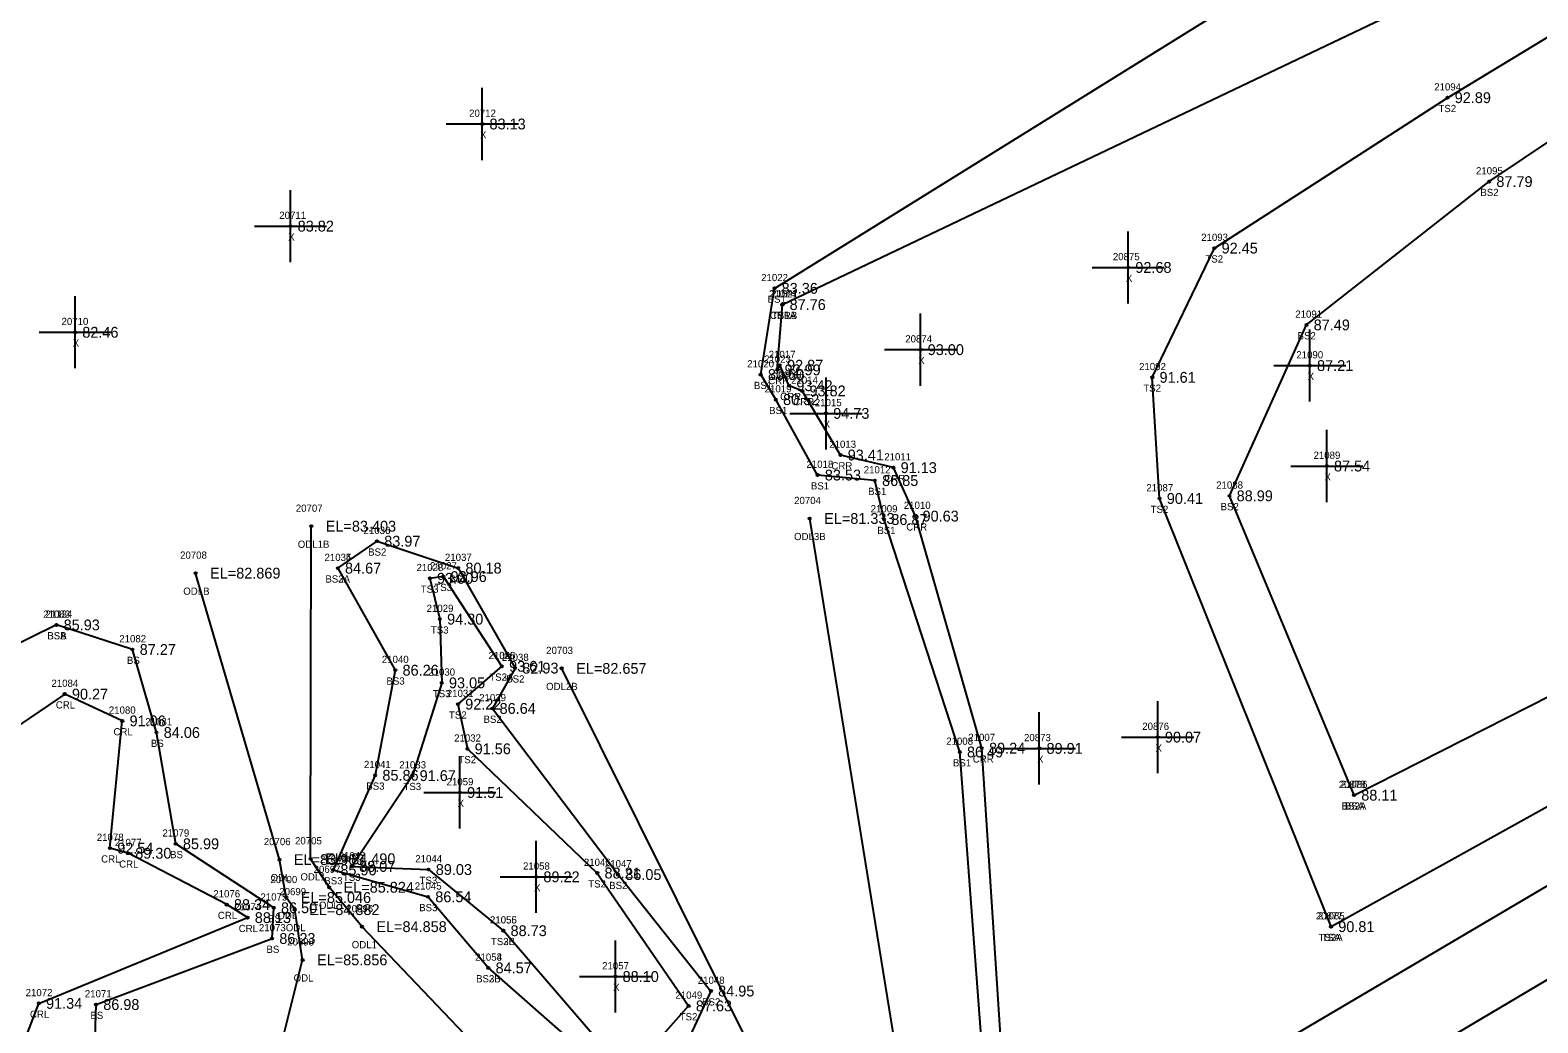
# Model space of a CAD drawing. Extents: x 2530197 to 2532051, y 935230 to 936631.
# Drawn here: x 2531049.2 to 2531258.3, y 936035.9 to 936173.5 of the extents above; entities that cross this region are included whole.
import ezdxf

# ---------------------------------------------------------------- set-up
doc = ezdxf.new("R2010")
doc.units = 0
for name, color, linetype in [('RD_DTM_BkLn1', 7, 'Continuous'), ('RD_DTM_BkLn2', 7, 'Continuous'), ('RD_DTM_BkLn_txCode', 7, 'Continuous'), ('RD_EX_H2O', 7, 'Continuous'), ('RD_EX_H2O_txCode', 7, 'Continuous'), ('RD_EX_Misc', 7, 'Continuous'), ('RD_EX_Misc_txCode', 7, 'Continuous'), ('RD_EX_Road', 7, 'Continuous'), ('RD_EX_TX_H2O_ELEV', 7, 'Continuous'), ('RD_EX_TX_Misc_ELEV', 7, 'Continuous'), ('RD_SMD_Locator', 7, 'Continuous')]:
    doc.layers.add(name, color=color, linetype=linetype)

msp = doc.modelspace()

# ---------------------------------------------------------------- linework, layer by layer
at = {"layer": 'RD_DTM_BkLn1'}
msp.add_lwpolyline([(2531175.16, 935992.09), (2531214.08, 936014.93), (2531297.2, 936064.16), (2531382.2, 936114.3), (2531466.12, 936163.77), (2531548.89, 936212.96), (2531632.55, 936261.89), (2531678, 936289.19), (2531722.34, 936315.93), (2531754.26, 936342.49), (2531759.78, 936349.83), (2531772.77, 936373.29), (2531778.96, 936389.71), (2531793.78, 936438.29), (2531813.65, 936511.36), (2531832.39, 936582.88)], dxfattribs=at)
at = {"layer": 'RD_DTM_BkLn2'}
for points in [[(2531151.41, 935999.3), (2531167.24, 936008.08), (2531181.24, 936018.79), (2531181.58, 936027.3), (2531178.12, 936073.45), (2531167.63, 936105.68), (2531166.35, 936111.09), (2531158.41, 936111.85), (2531152.62, 936122.31), (2531150.51, 936125.78), (2531152.42, 936137.74), (2531230.98, 936186.53), (2531313.57, 936233.84), (2531368.67, 936272.3), (2531431.6, 936307.72), (2531489.09, 936344.56)], [(2531153.52, 936135.49), (2531238.65, 936176.03), (2531319.12, 936225.52), (2531376.31, 936260.58), (2531439.07, 936295.88), (2531496.33, 936332.58)], [(2531229.61, 936049.23), (2531205.83, 936108.6), (2531204.82, 936125.4), (2531213.43, 936143.32), (2531245.76, 936164.18), (2531307.39, 936201.57), (2531320.27, 936194.22), (2531339.05, 936206.18), (2531339.67, 936220.33), (2531381.85, 936240.08), (2531451.4, 936278.23)], [(2531232.8, 936067.46), (2531215.52, 936108.97), (2531226.2, 936132.67), (2531251.54, 936152.54), (2531308.69, 936190.88), (2531325.04, 936186.59), (2531344.92, 936198.09), (2531350.73, 936212.74), (2531384.02, 936231.34), (2531448.45, 936270.32)], [(2531232.8, 936067.46), (2531281.18, 936092.01), (2531356.28, 936135.72), (2531362.71, 936151.65), (2531400.38, 936163.66), (2531430.03, 936179.35), (2531446.05, 936177.07), (2531452.65, 936188.16), (2531481.32, 936210.45), (2531494.44, 936219.29)], [(2531229.61, 936049.23), (2531287.21, 936081.23), (2531360.99, 936124.94), (2531368.39, 936145.81), (2531399.09, 936157.58), (2531431.15, 936172.97), (2531448.86, 936171.41), (2531455.43, 936183.06), (2531483.94, 936207.52), (2531496.93, 936216.06)], [(2531052.84, 936091.07), (2531024.22, 936076.99), (2530987.08, 936088.8), (2530959.02, 936078.33), (2530937.87, 936100.94), (2530909.67, 936126.05), (2530891.79, 936131.19), (2530874.19, 936136.38), (2530849.99, 936134.78), (2530837.59, 936141.92), (2530795.33, 936166.72)], [(2531091.86, 936098.94), (2531097.3, 936102.68), (2531108.56, 936098.95), (2531116.45, 936085.08), (2531113.3, 936079.49), (2531130.73, 936056.45), (2531143.61, 936040.3), (2531137.78, 936027.8), (2531130.84, 936027.63), (2531112.74, 936043.51)], [(2531091.86, 936098.94), (2531099.84, 936084.79), (2531097.05, 936070.22), (2531091.22, 936057.09), (2531104.38, 936053.37), (2531112.74, 936043.51)], [(2531114.62, 936085.33), (2531106.5, 936097.77), (2531104.62, 936097.53), (2531106.02, 936091.87), (2531106.28, 936083.04), (2531102.21, 936070.17), (2531093.82, 936057.58), (2531104.45, 936057.15), (2531114.82, 936048.67)], [(2531095.07, 935962.75), (2531085.58, 935955.64), (2531075.72, 935969.56), (2531061.95, 935983.33), (2531057.75, 936018.9), (2531058.33, 936038.43), (2531082.75, 936047.59), (2531082.98, 936051.85), (2531069.38, 936060.72), (2531066.72, 936076.15), (2531063.39, 936087.66), (2531052.84, 936091.07)], [(2531114.62, 936085.33), (2531108.53, 936080.08), (2531109.84, 936073.89), (2531127.85, 936056.66), (2531140.52, 936038.24), (2531132.03, 936028.68), (2531114.82, 936048.67)]]:
    msp.add_lwpolyline(points, dxfattribs=at)
at = {"layer": 'RD_EX_H2O'}
for points in [[(2531078.88, 935952.28), (2531078.88, 935952.28), (2531082.9, 935955.37), (2531071.89, 935962.43), (2531052.52, 935981.82), (2531042.66, 936018.54), (2531050.4, 936038.59), (2531079.35, 936050.48), (2531076.46, 936052.29), (2531062.77, 936059.41), (2531060.27, 936060.12), (2531061.98, 936077.76), (2531053.99, 936081.48), (2531023.23, 936060.57), (2531009.04, 936063.64), (2530981.92, 936072.85), (2530952.28, 936069.69), (2530922.53, 936086.42), (2530896.36, 936118.01), (2530886.54, 936120.09), (2530870.44, 936126.5), (2530844.88, 936119.11), (2530827.4, 936131.93), (2530794.88, 936161.74)], [(2531169.61, 936003.09), (2531185.12, 936014.09), (2531186.37, 936023.16), (2531184.04, 936029.91), (2531181.18, 936073.98), (2531171.96, 936106.16), (2531168.92, 936112.88), (2531161.58, 936114.63), (2531156.28, 936123.52), (2531154.46, 936124.24), (2531153.17, 936127.08), (2531152.81, 936126.44), (2531153.52, 936135.49)], [(2531123.96, 935982.91), (2531112.3, 936031.32), (2531095.21, 936049.23), (2531090.66, 936054.69), (2531088.09, 936058.64), (2531088.19, 936104.76)], [(2531151.41, 935999.3), (2531169.2, 936032.55), (2531157.31, 936105.83)], [(2531095.07, 935962.75), (2531077.48, 936006.74), (2531086.98, 936044.62), (2531085.89, 936051.59), (2531084.72, 936053.27), (2531083.78, 936058.53), (2531072.15, 936098.25)], [(2531140.12, 935992.42), (2531149.6, 936031.44), (2531122.92, 936085.04)]]:
    msp.add_lwpolyline(points, dxfattribs=at)
at = {"layer": 'RD_EX_Misc'}
for p, q in [((2531111.9, 936155.53), (2531111.9, 936165.53)), ((2531106.9, 936160.53), (2531116.9, 936160.53)), ((2531085.3, 936141.37), (2531085.3, 936151.37)), ((2531080.3, 936146.37), (2531090.3, 936146.37)), ((2531201.47, 936135.64), (2531201.47, 936145.64)), ((2531196.47, 936140.64), (2531206.47, 936140.64)), ((2531055.43, 936126.65), (2531055.43, 936136.65)), ((2531172.67, 936124.24), (2531172.67, 936134.24)), ((2531050.43, 936131.65), (2531060.43, 936131.65)), ((2531226.67, 936122.03), (2531226.67, 936132.03)), ((2531167.67, 936129.24), (2531177.67, 936129.24)), ((2531221.67, 936127.03), (2531231.67, 936127.03)), ((2531159.57, 936115.4), (2531159.57, 936125.4)), ((2531154.57, 936120.4), (2531164.57, 936120.4)), ((2531229.02, 936108.1), (2531229.02, 936118.1)), ((2531224.02, 936113.1), (2531234.02, 936113.1)), ((2531189.15, 936068.95), (2531189.15, 936078.95)), ((2531205.57, 936070.51), (2531205.57, 936080.51)), ((2531200.57, 936075.51), (2531210.57, 936075.51)), ((2531108.79, 936062.83), (2531108.79, 936072.83)), ((2531184.15, 936073.95), (2531194.15, 936073.95)), ((2531103.79, 936067.83), (2531113.79, 936067.83)), ((2531119.38, 936051.14), (2531119.38, 936061.14)), ((2531114.38, 936056.14), (2531124.38, 936056.14)), ((2531130.36, 936037.31), (2531130.36, 936047.31)), ((2531125.36, 936042.31), (2531135.36, 936042.31))]:
    msp.add_line(p, q, dxfattribs=at)
at = {"layer": 'RD_EX_Road'}
msp.add_lwpolyline([(2531169.65, 936000.77), (2531208.79, 936024.95), (2531292.04, 936074.02), (2531376.24, 936123.7), (2531460.37, 936174.49), (2531542.92, 936223.44), (2531626.67, 936270.85), (2531672.4, 936298.39), (2531714.28, 936327.21), (2531747.19, 936360.45), (2531761.42, 936377.32), (2531773.11, 936411.11), (2531782.2, 936441.65), (2531803.17, 936514.76), (2531820.28, 936585.8)], dxfattribs=at)
at = {"layer": 'RD_SMD_Locator'}
for centre in [(2531245.76, 936164.18), (2531111.9, 936160.53), (2531251.54, 936152.54), (2531085.3, 936146.37), (2531213.43, 936143.32), (2531201.47, 936140.64), (2531152.42, 936137.74), (2531153.52, 936135.49), (2531153.52, 936135.49), (2531055.43, 936131.65), (2531226.2, 936132.67), (2531172.67, 936129.24), (2531153.17, 936127.08), (2531226.67, 936127.03), (2531150.51, 936125.78), (2531152.81, 936126.44), (2531204.82, 936125.4), (2531154.46, 936124.24), (2531156.28, 936123.52), (2531152.62, 936122.31), (2531159.57, 936120.4), (2531161.58, 936114.63), (2531168.92, 936112.88), (2531229.02, 936113.1), (2531158.41, 936111.85), (2531166.35, 936111.09), (2531205.83, 936108.6), (2531215.52, 936108.97), (2531157.31, 936105.83), (2531171.96, 936106.16), (2531088.19, 936104.76), (2531167.63, 936105.68), (2531097.3, 936102.68), (2531072.15, 936098.25), (2531091.86, 936098.94), (2531091.86, 936098.94), (2531104.62, 936097.53), (2531106.5, 936097.77), (2531108.56, 936098.95), (2531106.02, 936091.87), (2531052.84, 936091.07), (2531052.84, 936091.07), (2531063.39, 936087.66), (2531114.62, 936085.33), (2531114.62, 936085.33), (2531116.45, 936085.08), (2531122.92, 936085.04), (2531099.84, 936084.79), (2531106.28, 936083.04), (2531053.99, 936081.48), (2531108.53, 936080.08), (2531113.3, 936079.49), (2531061.98, 936077.76), (2531066.72, 936076.15), (2531205.57, 936075.51), (2531109.84, 936073.89), (2531178.12, 936073.45), (2531181.18, 936073.98), (2531189.15, 936073.95), (2531097.05, 936070.22), (2531102.21, 936070.17), (2531108.79, 936067.83), (2531232.8, 936067.46), (2531232.8, 936067.46), (2531060.27, 936060.12), (2531069.38, 936060.72), (2531062.77, 936059.41), (2531083.78, 936058.53), (2531088.09, 936058.64), (2531091.22, 936057.09), (2531093.82, 936057.58), (2531104.45, 936057.15), (2531119.38, 936056.14), (2531127.85, 936056.66), (2531130.73, 936056.45), (2531090.66, 936054.69), (2531076.46, 936052.29), (2531082.98, 936051.85), (2531084.72, 936053.27), (2531085.89, 936051.59), (2531104.38, 936053.37), (2531079.35, 936050.48), (2531082.75, 936047.59), (2531095.21, 936049.23), (2531114.82, 936048.67), (2531114.82, 936048.67), (2531229.61, 936049.23), (2531229.61, 936049.23), (2531086.98, 936044.62), (2531112.74, 936043.51), (2531112.74, 936043.51), (2531130.36, 936042.31), (2531143.61, 936040.3), (2531050.4, 936038.59), (2531058.33, 936038.43), (2531140.52, 936038.24)]:
    msp.add_circle(centre, 0.15, dxfattribs=at)

# ---------------------------------------------------------------- texts
at = {"layer": 'RD_DTM_BkLn_txCode'}
for s, p in [('21094', (2531243.92, 936165.18)), ('TS2', (2531244.51, 936162.18)), ('21095', (2531249.71, 936153.54)), ('BS2', (2531250.32, 936150.54)), ('21093', (2531211.6, 936144.32)), ('TS2', (2531212.19, 936141.32)), ('21022', (2531150.58, 936138.74)), ('21021', (2531151.97, 936136.49)), ('BS1', (2531151.47, 936135.74)), ('TS1A', (2531152.07, 936133.49)), ('21091', (2531224.65, 936133.67)), ('BS2', (2531224.97, 936130.67)), ('21020', (2531148.64, 936126.78)), ('21092', (2531202.99, 936126.4)), ('BS1', (2531149.57, 936123.78)), ('21019', (2531151.06, 936123.31)), ('TS2', (2531203.58, 936123.4)), ('BS1', (2531151.67, 936120.31)), ('21018', (2531156.86, 936112.85)), ('21012', (2531164.8, 936112.09)), ('BS1', (2531157.47, 936109.85)), ('21087', (2531204, 936109.6)), ('21088', (2531213.68, 936109.97)), ('BS1', (2531165.41, 936109.09)), ('21009', (2531165.76, 936106.68)), ('TS2', (2531204.59, 936106.6)), ('BS2', (2531214.29, 936106.97)), ('21036', (2531095.44, 936103.68)), ('BS1', (2531166.69, 936103.68)), ('21034', (2531090.02, 936099.94)), ('21035', (2531090.02, 936099.94)), ('BS2', (2531096.07, 936100.68)), ('21027', (2531104.66, 936098.77)), ('21037', (2531106.72, 936099.95)), ('BS2A', (2531090.14, 936096.94)), ('BS3A', (2531090.14, 936096.94)), ('21028', (2531102.78, 936098.53)), ('BS2', (2531107.33, 936096.95)), ('TS3', (2531103.37, 936095.53)), ('TS3', (2531105.26, 936095.77)), ('21029', (2531104.18, 936092.87)), ('21083', (2531051.01, 936092.07)), ('21134', (2531051.33, 936092.07)), ('BSA', (2531051.57, 936089.07)), ('BSB', (2531051.59, 936089.07)), ('21082', (2531061.56, 936088.66)), ('TS3', (2531104.77, 936089.87)), ('21026', (2531112.76, 936086.33)), ('21025', (2531112.78, 936086.33)), ('BS', (2531062.62, 936085.66)), ('21040', (2531097.97, 936085.79)), ('21038', (2531114.62, 936086.08)), ('BS3', (2531098.61, 936082.79)), ('21030', (2531104.41, 936084.04)), ('TS2A', (2531112.88, 936083.33)), ('TS3A', (2531112.88, 936083.33)), ('BS2', (2531115.22, 936083.08)), ('TS3', (2531105.04, 936081.04)), ('21031', (2531106.98, 936081.08)), ('21039', (2531111.47, 936080.49)), ('TS2', (2531107.28, 936078.08)), ('21081', (2531065.17, 936077.15)), ('BS2', (2531112.07, 936077.49)), ('BS', (2531065.94, 936074.15)), ('21032', (2531108, 936074.89)), ('21008', (2531176.24, 936074.45)), ('TS2', (2531108.59, 936071.89)), ('21041', (2531095.49, 936071.22)), ('21033', (2531100.38, 936071.17)), ('BS1', (2531177.17, 936071.45)), ('BS3', (2531095.82, 936068.22)), ('TS3', (2531100.97, 936068.17)), ('20878', (2531230.68, 936068.46)), ('21086', (2531230.94, 936068.46)), ('BS2A', (2531231.08, 936065.46)), ('BSA', (2531231.53, 936065.46)), ('21079', (2531067.54, 936061.72)), ('BS', (2531068.6, 936058.72)), ('21043', (2531089.39, 936058.09)), ('21042', (2531091.98, 936058.58)), ('21044', (2531102.61, 936058.15)), ('21046', (2531125.99, 936057.66)), ('21047', (2531128.9, 936057.45)), ('BS3', (2531089.99, 936055.09)), ('TS3', (2531092.57, 936055.58)), ('TS3', (2531103.2, 936055.15)), ('21075', (2531081.14, 936052.85)), ('21045', (2531102.54, 936054.37)), ('TS2', (2531126.6, 936054.66)), ('BS2', (2531129.5, 936054.45)), ('BS3', (2531103.15, 936051.37)), ('21073', (2531080.92, 936048.59)), ('BS', (2531082.2, 936049.85)), ('21056', (2531112.96, 936049.67)), ('21055', (2531112.98, 936049.67)), ('20877', (2531227.5, 936050.23)), ('21085', (2531227.78, 936050.23)), ('TS2B', (2531113.1, 936046.67)), ('TS3B', (2531113.1, 936046.67)), ('TS2A', (2531227.88, 936047.23)), ('TSA', (2531228.33, 936047.23)), ('BS', (2531081.97, 936045.59)), ('21053', (2531110.91, 936044.51)), ('21054', (2531110.91, 936044.51)), ('BS2B', (2531111.04, 936041.51)), ('BS3B', (2531111.04, 936041.51)), ('21048', (2531141.78, 936041.3)), ('21071', (2531056.78, 936039.43)), ('21049', (2531138.69, 936039.24)), ('BS2', (2531142.38, 936038.3)), ('BS', (2531057.55, 936036.43)), ('TS2', (2531139.28, 936036.24))]:
    msp.add_text(s, height=1, dxfattribs=at).set_placement(p)
at = {"layer": 'RD_EX_H2O_txCode'}
for s, p in [('21024', (2531151.68, 936136.49)), ('CRRB', (2531151.79, 936133.49)), ('21017', (2531151.62, 936128.08)), ('21023', (2531150.98, 936127.44)), ('CRR', (2531151.56, 936124.44)), ('CRR', (2531151.92, 936125.08)), ('21016', (2531152.89, 936125.24)), ('21014', (2531154.73, 936124.52)), ('CRR', (2531153.21, 936122.24)), ('CRR', (2531155.03, 936121.52)), ('21013', (2531160.02, 936115.63)), ('21011', (2531167.65, 936113.88)), ('CRR', (2531160.32, 936112.63)), ('CRR', (2531167.66, 936110.88)), ('20704', (2531155.15, 936107.83)), ('21010', (2531170.36, 936107.16)), ('20707', (2531086.04, 936106.76)), ('CRR', (2531170.7, 936104.16)), ('ODL1B', (2531086.31, 936101.76)), ('ODL3B', (2531155.14, 936102.83)), ('20708', (2531069.99, 936100.25)), ('ODLB', (2531070.43, 936095.25)), ('20703', (2531120.76, 936087.04)), ('21084', (2531052.15, 936082.48)), ('ODL2B', (2531120.75, 936082.04)), ('CRL', (2531052.76, 936079.48)), ('21080', (2531060.11, 936078.76)), ('CRL', (2531060.75, 936075.76)), ('21007', (2531179.3, 936074.98)), ('CRR', (2531179.93, 936071.98)), ('21078', (2531058.44, 936061.12)), ('21077', (2531060.93, 936060.41)), ('20706', (2531081.6, 936060.53)), ('20705', (2531085.93, 936060.64)), ('CRL', (2531059.04, 936058.12)), ('CRL', (2531061.54, 936057.41)), ('20700', (2531082.52, 936055.27)), ('ODL', (2531082.54, 936055.53)), ('ODL1', (2531086.68, 936055.64)), ('20697', (2531088.51, 936056.69)), ('21076', (2531074.6, 936053.29)), ('20699', (2531083.75, 936053.59)), ('21074', (2531077.52, 936051.48)), ('ODL1', (2531089.25, 936051.69)), ('20696', (2531093.04, 936051.23)), ('CRL', (2531075.23, 936050.29)), ('ODL', (2531083.48, 936050.27)), ('ODL', (2531084.65, 936048.59)), ('CRL', (2531078.12, 936048.48)), ('20698', (2531084.84, 936046.62)), ('ODL1', (2531093.8, 936046.23)), ('ODL', (2531085.74, 936041.62)), ('21072', (2531048.57, 936039.59)), ('CRL', (2531049.17, 936036.59))]:
    msp.add_text(s, height=1, dxfattribs=at).set_placement(p)
at = {"layer": 'RD_EX_Misc_txCode'}
for s, p in [('20712', (2531110.07, 936161.53)), ('X', (2531111.59, 936158.53)), ('20711', (2531083.75, 936147.37)), ('X', (2531084.99, 936144.37)), ('20875', (2531199.35, 936141.64)), ('X', (2531201.16, 936138.64)), ('20710', (2531053.55, 936132.65)), ('20874', (2531170.56, 936130.24)), ('X', (2531055.11, 936129.65)), ('21090', (2531224.8, 936128.03)), ('X', (2531172.36, 936127.24)), ('X', (2531226.36, 936125.03)), ('21015', (2531158.02, 936121.4)), ('X', (2531159.25, 936118.4)), ('21089', (2531227.18, 936114.1)), ('X', (2531228.7, 936111.1)), ('20876', (2531203.43, 936076.51)), ('20873', (2531187.03, 936074.95)), ('X', (2531188.84, 936071.95)), ('X', (2531205.26, 936073.51)), ('21059', (2531106.95, 936068.83)), ('X', (2531108.47, 936065.83)), ('21058', (2531117.55, 936057.14)), ('X', (2531119.07, 936054.14)), ('21057', (2531128.52, 936043.31)), ('X', (2531130.04, 936040.31))]:
    msp.add_text(s, height=1, dxfattribs=at).set_placement(p)
at = {"layer": 'RD_EX_TX_H2O_ELEV'}
for s, p in [('87.76', (2531154.52, 936134.74)), ('92.99', (2531153.81, 936125.69)), ('92.87', (2531154.17, 936126.33)), ('93.42', (2531155.46, 936123.49)), ('93.82', (2531157.28, 936122.77)), ('93.41', (2531162.58, 936113.88)), ('91.13', (2531169.92, 936112.13)), ('EL=81.333', (2531159.31, 936105.08)), ('90.63', (2531172.96, 936105.41)), ('EL=83.403', (2531090.19, 936104.01)), ('EL=82.869', (2531074.15, 936097.5)), ('EL=82.657', (2531124.92, 936084.29)), ('90.27', (2531054.99, 936080.73)), ('91.06', (2531062.98, 936077.01)), ('89.24', (2531182.18, 936073.23)), ('92.54', (2531061.27, 936059.37)), ('89.30', (2531063.77, 936058.66)), ('EL=83.963', (2531085.78, 936057.78)), ('EL=84.490', (2531090.09, 936057.89)), ('EL=85.046', (2531086.72, 936052.52)), ('EL=85.824', (2531092.66, 936053.94)), ('88.34', (2531077.46, 936051.54)), ('EL=84.882', (2531087.89, 936050.84)), ('88.13', (2531080.35, 936049.73)), ('EL=84.858', (2531097.21, 936048.48)), ('EL=85.856', (2531088.98, 936043.87)), ('91.34', (2531051.4, 936037.84))]:
    msp.add_text(s, height=1.5, dxfattribs=at).set_placement(p)
at = {"layer": 'RD_EX_TX_Misc_ELEV'}
for s, p in [('92.89', (2531246.76, 936163.43)), ('83.13', (2531112.9, 936159.78)), ('87.79', (2531252.54, 936151.79)), ('83.82', (2531086.3, 936145.62)), ('92.45', (2531214.43, 936142.57)), ('92.68', (2531202.47, 936139.89)), ('83.36', (2531153.42, 936136.99)), ('87.76', (2531154.52, 936134.74)), ('87.49', (2531227.2, 936131.92)), ('82.46', (2531056.43, 936130.9)), ('93.00', (2531173.67, 936128.49)), ('87.21', (2531227.67, 936126.28)), ('80.60', (2531151.51, 936125.03)), ('91.61', (2531205.82, 936124.65)), ('80.52', (2531153.62, 936121.56)), ('94.73', (2531160.57, 936119.65)), ('83.53', (2531159.41, 936111.1)), ('87.54', (2531230.02, 936112.35)), ('86.85', (2531167.35, 936110.34)), ('90.41', (2531206.83, 936107.85)), ('88.99', (2531216.52, 936108.22)), ('86.87', (2531168.63, 936104.93)), ('83.97', (2531098.3, 936101.93)), ('84.67', (2531092.86, 936098.19)), ('84.67', (2531092.86, 936098.19)), ('80.18', (2531109.56, 936098.2)), ('93.00', (2531105.62, 936096.78)), ('92.96', (2531107.5, 936097.02)), ('85.93', (2531053.84, 936090.32)), ('85.93', (2531053.84, 936090.32)), ('94.30', (2531107.02, 936091.12)), ('87.27', (2531064.39, 936086.91)), ('86.26', (2531100.84, 936084.04)), ('93.61', (2531115.62, 936084.58)), ('93.61', (2531115.62, 936084.58)), ('82.93', (2531117.45, 936084.33)), ('93.05', (2531107.28, 936082.29)), ('92.22', (2531109.53, 936079.33)), ('86.64', (2531114.3, 936078.74)), ('84.06', (2531067.72, 936075.4)), ('91.56', (2531110.84, 936073.14)), ('89.91', (2531190.15, 936073.2)), ('90.07', (2531206.57, 936074.76)), ('86.49', (2531179.12, 936072.7)), ('85.86', (2531098.05, 936069.47)), ('91.67', (2531103.21, 936069.42)), ('91.51', (2531109.79, 936067.08)), ('88.11', (2531233.8, 936066.71)), ('88.11', (2531233.8, 936066.71)), ('85.99', (2531070.38, 936059.97)), ('88.07', (2531094.82, 936056.83)), ('89.03', (2531105.45, 936056.4)), ('85.90', (2531092.22, 936056.34)), ('89.22', (2531120.38, 936055.39)), ('88.21', (2531128.85, 936055.91)), ('86.05', (2531131.73, 936055.7)), ('86.54', (2531105.38, 936052.62)), ('86.50', (2531083.98, 936051.1)), ('90.81', (2531230.61, 936048.48)), ('90.81', (2531230.61, 936048.48)), ('86.23', (2531083.75, 936046.84)), ('88.73', (2531115.82, 936047.92)), ('88.73', (2531115.82, 936047.92)), ('84.57', (2531113.74, 936042.76)), ('84.57', (2531113.74, 936042.76)), ('88.10', (2531131.36, 936041.56)), ('86.98', (2531059.33, 936037.68)), ('84.95', (2531144.61, 936039.55)), ('87.63', (2531141.52, 936037.49))]:
    msp.add_text(s, height=1.5, dxfattribs=at).set_placement(p)

doc.saveas('drawing.dxf')
